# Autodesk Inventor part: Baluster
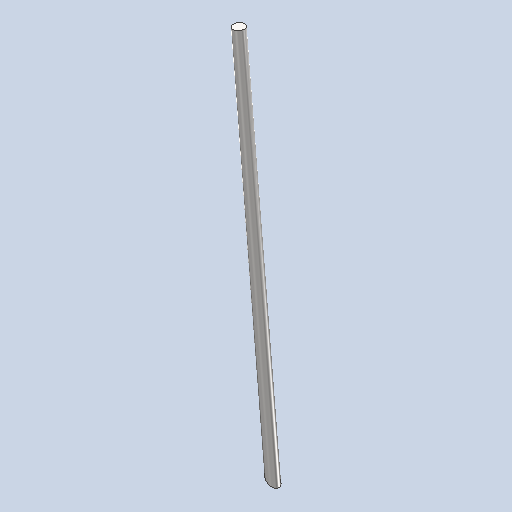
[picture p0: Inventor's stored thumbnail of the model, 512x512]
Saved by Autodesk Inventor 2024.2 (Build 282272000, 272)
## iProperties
Created: 2022-06
Part Number: Baluster
Material: Steel, Galvanized
Document SubType Name: Modeling
Designer: reaumed
Density: 7.85 g/cm^3
Appearance: Galvanized
Mass: 3323.97 g
Surface Area: 678.138 cm^2
Volume: 423.435 cm^3
Author: reaumed
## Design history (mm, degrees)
workplane "Work Plane1"
workplane "Work Plane2"
workplane "Work Plane3"
sketch "Sketch1"
  geometry: L1 (-1199.072, 361.95)-(1779.005, 361.95) reference; L2 (114.3, 601.98)-(114.3, -100.33) reference; C1 r 12.7 at (114.3, 361.95); 1 further point
  constraints: 1 centre point
  dimensions: "d3" = 0 distance from line of C1.centre L1; "d4" = 0 distance from line of L2 C1.centre; "d7" = 25.4 diameter of C1 (= BalusterDia)
extrude "Extrusion1" new body sketch "Sketch1" distance "d5" = 927.1 (= BalusterLength + 0.5 x BalusterDia); taper "d6" = 0 deg
sketch "Sketch2"
  geometry: L1 (-228.6, -190.5)-(-1353.565, -1127.971); L2 (0, -190.5)-(-228.6, -190.5); L3 (773.632, -1127.971)-(-1353.565, -1127.971); 1 further point
  constraints: 6 end point, 2 horizontal
  dimensions: "d8" = 190.5 distance from line of L2 point (0, 0) (= Rise); "d9" = 228.6 horizontal distance of L1.start point (0, 0) (= Run); "d10" = 39.8056 deg angle of L3 L1 (= TheAngle)
workplane "Work Plane7"
split "Split4"
body "Solid1"
other parameters: "Rise" = 190.5 [user parameter; used in 2 equation terms], "Run" = 228.6 [user parameter; used in 2 equation terms], "Width" = 762 [user parameter; used in 1 equation term], "d0" = -190.5 (= -Rise), "d1" = 361.95 (= 0.5 x Width - 0.5 x StringerThickness), "d2" = 114.3 (= 0.5 x Run), "BalusterDia" = 25.4 [user parameter; used in 2 equation terms], "BalusterLength" = 914.4 [user parameter; used in 1 equation term], "StringerThickness" = 38.1 [user parameter; used in 1 equation term], "TreadThickness" = 31.75 [user parameter], "d11" = 90 deg, "TheAngle" = 39.8056 deg [user parameter; used in 1 equation term]
